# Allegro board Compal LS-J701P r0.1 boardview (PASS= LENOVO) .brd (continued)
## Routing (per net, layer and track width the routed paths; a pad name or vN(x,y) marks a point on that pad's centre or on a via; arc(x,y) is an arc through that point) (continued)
USB3_RX3_CONN1_P1_R: length 13.1
  BOTTOM w0.117: JUSB1.6 19.17,65.66 19.05,65.78 18.22,65.78 17.91,66.09 17.91,67.26 17.71,67.46 17.06,67.46 16.94,67.35 16.94,64.72 17.12,64.54 v4(17.42,64.54) 17.74,64.54 17.99,64.29 17.99,63.52 17.37,62.9 17.11,62.9 16.97,62.76 D1.2 D1.8 15.11,62.76 14.97,62.9 14.74,62.9 RT53.2
USB3_RX3_CONN2_N2: length 11.1
  TOP w0.117: v1(8.78,48.62) 9.61,48.62 10.59,49.59 10.59,49.9 10.61,49.92 10.61,50.47 10.59,50.5 10.59,52.11 10.59,52.11 10.59,52.77 RT56.1
  BOTTOM w0.117: UT2.8 10.43,45.85 10.57,45.99 v4(10.57,47.11) 10.57,47.96 9.55,48.98 9.24,48.98 9.16,48.91 9.16,48.67 9.11,48.62 v1(8.78,48.62)
USB3_RX3_CONN2_N2_R: length 25.6
  TOP w0.117: v1(10.29,58.2) 10.11,58.02 10.11,57.37 10.53,56.95 10.53,56.64 10.67,56.5 D3.1 D3.9 10.67,54.81 10.59,54.73 10.59,54.29 RT56.2
  IN2 w0.127: JUSB2.5 19.17,45.14 19.04,45.01 18.79,45.01 17.8,46 17.8,47.72 16.33,49.18 11.7,49.18 10.22,50.67 10.22,57.14 10.12,57.24 10.12,58.02 v1(10.29,58.2)
USB3_RX3_CONN2_P2: length 11.1
  TOP w0.117: v1(8.78,49.2) 9.03,49.2 9.1,49.14 9.1,48.96 9.21,48.84 9.52,48.84 10.36,49.68 v4(10.36,50.2) 10.36,52.2 10.36,52.77 RT55.1
  BOTTOM w0.117: v1(8.78,49.2) 9.65,49.2 10.79,48.05 10.79,47.41 10.82,47.38 10.82,46.83 10.79,46.81 10.79,45.99 10.93,45.85 UT2.9
USB3_RX3_CONN2_P2_R: length 25.6
  TOP w0.117: RT55.2 10.36,54.29 10.36,54.71 10.17,54.9 D3.8 D3.2 10.17,56.47 10.31,56.61 10.31,56.86 9.89,57.28 9.89,58.02 v1(9.71,58.2)
  IN2 w0.127: v1(9.71,58.2) 9.89,58.02 9.89,57.15 9.99,57.05 9.99,50.57 11.61,48.96 16.24,48.96 17.57,47.63 17.57,45.91 18.7,44.79 18.95,44.79 19.17,44.57 JUSB2.6
USB3_TX3_CONN1_N1: length 18.4
  IN1 w0.102: v1(12.91,61.71) 13.1,61.51 13.3,61.51 13.95,62.16 13.95,72.35 11.58,74.72 11.58,76.05 v1(11.19,76.44)
  BOTTOM w0.117: v1(12.91,61.71) 13.09,61.53 13.28,61.53 RT58.1 ; CT18.2 11.4,76.1 11.4,76.23 v1(11.19,76.44)
USB3_TX3_CONN1_N1_R: length 6.8
  BOTTOM w0.117: RT58.2 14.69,61.63 15,61.63 15.14,61.76 D1.7 D1.4 16.71,61.76 16.94,61.53 v4(17.45,61.53) 17.83,61.53 18.18,61.18 18.18,60.46 18.65,59.99 19.05,59.99 19.17,60.11 JUSB1.8
USB3_TX3_CONN1_P1: length 18.5
  IN1 w0.102: v1(12.91,61.12) 13.1,61.32 13.38,61.32 14.14,62.08 14.14,72.43 11.77,74.8 v1(11.77,76.44)
  BOTTOM w0.117: v1(12.91,61.12) 13.09,61.3 13.28,61.3 RT57.1 ; v1(11.77,76.44) 11.64,76.31 11.64,76.01 CT17.2
USB3_TX3_CONN1_P1_R: length 6.8
  BOTTOM w0.117: RT57.2 14.89,61.4 15,61.4 15.14,61.26 D1.6 D1.5 16.8,61.26 16.85,61.31 17.1,61.31 17.12,61.28 17.76,61.28 17.96,61.09 17.96,60.36 18.55,59.76 19.05,59.76 19.17,59.65 JUSB1.9
USB3_TX3_CONN2_N2: length 12.8
  TOP w0.117: RT59.1 8.94,52.77 8.94,51.9 9.18,51.66 9.37,51.66 v1(9.55,51.84)
  BOTTOM w0.117: v1(9.55,51.84) 9.36,51.65 8.04,51.65 7.92,51.53 7.8,51.4 7.8,50.66 8.11,50.35 8.81,50.35 9.19,49.97 9.78,49.97 9.81,49.95 10.36,49.95 10.38,49.97 v4(11.52,49.97) 12.12,49.97 12.68,49.4 12.68,48.81 12.07,48.19 12.07,47.35 CT25.2
USB3_TX3_CONN2_N2_R: length 30.9
  TOP w0.117: RT59.2 8.94,54.29 8.94,54.7 9.17,54.94 D3.7 D3.4 9.17,56.47 9.03,56.61 9.03,57.2 v1(9.21,57.38)
  IN2 w0.127: JUSB2.8 19.17,39.2 19.04,39.08 18.06,39.08 17.13,40 17.13,47.45 16.06,48.53 11.02,48.53 10.15,49.39 9.03,50.52 9.03,57.21 v1(9.21,57.38)
USB3_TX3_CONN2_P2: length 12.7
  TOP w0.117: v1(9.55,51.25) 9.37,51.43 9.09,51.43 8.71,51.81 8.71,52.77 RT60.1
  BOTTOM w0.117: CT24.2 12.29,47.35 12.29,48.1 12.91,48.72 12.91,49.5 12.21,50.2 11.82,50.2 11.8,50.22 11.25,50.22 11.22,50.2 v4(10.08,50.2) 9.28,50.2 8.91,50.57 8.2,50.57 8.02,50.75 8.02,51.31 8.14,51.43 9.37,51.43 v1(9.55,51.25)
USB3_TX3_CONN2_P2_R: length 30.9
  TOP w0.117: RT60.2 8.71,54.29 8.71,54.7 8.67,54.75 D3.6 D3.5 8.67,56.5 8.81,56.64 8.81,57.2 v1(8.63,57.38)
  IN2 w0.127: v1(8.63,57.38) 8.81,57.21 8.81,50.42 9.61,49.62 10.93,48.3 15.97,48.3 16.91,47.36 16.91,39.91 17.97,38.85 19.04,38.85 19.17,38.72 JUSB2.9
USB3_TX3_MUX_N1_C: length 1.5
  BOTTOM w0.117: CT18.1 11.34,75.16 11.34,74.64 11.2,74.5 UT1.11
USB3_TX3_MUX_N2_C: length 1.5
  BOTTOM w0.117: UT2.11 11.93,45.85 12.07,45.99 12.07,46.41 CT25.1
USB3_TX3_MUX_P1_C: length 1.5
  BOTTOM w0.117: UT1.12 11.7,74.5 11.56,74.64 11.56,75.1 CT17.1
USB3_TX3_MUX_P2_C: length 1.5
  BOTTOM w0.117: UT2.12 12.43,45.85 12.3,45.99 12.3,46.42 CT24.1
USB20_N1: length 52.4
  TOP w0.117: L1.1 8.65,47.21 v1(8.61,47.25)
  IN1 w0.102: v1(26.61,8.98) 26.43,9.16 26.43,9.51 26.22,9.72 24.87,9.72 23.26,11.33 23.26,14.44 20.93,16.77 20.93,19.59 20.59,19.94 20.59,20.19 19.68,21.1 18.99,21.1 10.52,29.57 10.52,35.75 10.27,36.01 10.27,41.5 9.71,42.06 9.71,46.49 9.17,47.02 8.83,47.02 v1(8.61,47.25)
  BOTTOM w0.117: v1(26.61,8.98) 26.43,9.16 26.43,9.36 26.5,9.43 28.3,9.43 28.72,9.99 28.96,10.02 JIO2.2
USB20_N1_R: length 27.4
  TOP w0.117: L1.2 11,47.07 11.97,47.07 12.09,47.19 12.09,47.89 D2.6 12.4,47.19 12.52,47.07 12.82,47.07 v1(13,47.25)
  IN1 w0.102: v1(13,47.25) 12.92,47.17 12.78,47.17 12.7,47.25 12.7,57.72 16.1,61.12 16.99,61.12 18.24,62.37 18.24,63.58 18.45,63.78 19.44,63.78 20.67,62.56 JUSB1.2
USB20_N2: length 16.1
  TOP w0.117: v1(13.61,22.88) 13.43,22.7 13.14,22.7 13.12,22.73 12.57,22.73 12.54,22.7 11.07,22.7 10.24,23.53 10.24,29.05 10.72,29.52 v4(11.41,29.52) 12.11,29.52 13.53,30.94 13.53,31.22 L2.4
  BOTTOM w0.117: v1(13.61,22.88) 13.71,22.78 14.17,22.78 14.6,22.34 14.62,21.99 14.55,21.91 14.55,21.88 14.54,21.86 14.56,21.65 14.38,21.41 JIO2.39
USB20_N2_R: length 22.2
  TOP w0.117: L2.3 13.67,32.02 13.44,32.25 13.44,32.51 v1(13.71,32.78) ; v1(14.23,37.54) 14.24,37.54 14.42,37.36 14.53,37.36 14.64,37.48 D5.4 14.96,37.99 14.96,37.54 15.16,37.34 15.5,37.34 v1(15.77,37.6)
  IN1 w0.102: v1(15.77,37.6) 15.47,37.3 15.42,37.3 15.19,37.53 15.19,41.05 17.06,42.92 19.51,42.92 20.67,41.76 JUSB2.2 ; v1(13.71,32.78) 13.39,33.1 13.39,33.15 15.26,35.02 15.26,36.24 15.24,36.25 15.24,36.66 14.6,37.3 14.46,37.3 v1(14.23,37.54)
USB20_P1: length 52.5
  TOP w0.117: L1.4 10.19,46.71 9.92,46.98 9.92,46.98 9.06,46.98 8.97,46.89 8.97,46.7 8.93,46.66 v1(8.61,46.66)
  IN1 w0.102: v1(26.03,9.01) 26.24,9.23 26.24,9.43 26.14,9.53 24.79,9.53 23.07,11.25 23.07,14.37 20.74,16.69 20.74,19.51 20.4,19.86 20.4,20.11 19.6,20.91 18.91,20.91 10.33,29.49 10.33,35.68 10.08,35.93 10.08,41.42 9.52,41.98 9.52,46.41 9.09,46.83 8.78,46.83 v1(8.61,46.66)
  BOTTOM w0.117: v1(26.03,9.01) 26.21,9.19 26.21,9.46 26.4,9.65 28.19,9.65 28.54,10.12 28.52,10.27 28.75,10.58
USB20_P1_R: length 27.4
  TOP w0.117: v1(13,46.66) 12.82,46.85 12.52,46.85 12.4,46.73 D2.1 12.09,46.02 12.09,46.73 11.97,46.84 11,46.84 L1.3
  IN1 w0.102: v1(13,46.66) 12.8,46.86 12.8,46.87 12.51,47.17 12.51,57.79 16.02,61.31 16.91,61.31 18.05,62.45 18.05,63.66 18.37,63.97 19.52,63.97 20.03,63.47 20.24,63.47 JUSB1.3
USB20_P2: length 16
  TOP w0.117: L2.1 13.3,31.22 13.3,31.03 12.02,29.75 11.71,29.75 11.69,29.77 11.14,29.77 11.11,29.75 10.62,29.75 10.02,29.14 10.02,23.43 10.97,22.48 v4(12.84,22.48) 13.43,22.48 v1(13.61,22.3)
  BOTTOM w0.117: v1(13.61,22.3) 13.86,22.55 14.07,22.55 14.38,22.24 14.39,22.07 14.36,22.03 14.22,22.01 13.98,21.71 JIO2.40
USB20_P2_R: length 22.2
  TOP w0.117: v1(15.77,37.02) 15.67,37.11 15.08,37.11 14.96,37 14.96,36.12 D5.3 14.64,36.95 14.46,37.14 14.42,37.14 v1(14.24,36.95) ; v1(13.12,32.78) 13.17,32.74 L2.2
  IN1 w0.102: v1(14.24,36.95) 14.4,37.11 14.52,37.11 15.05,36.58 15.05,36.17 15.06,36.16 15.06,35.1 13.2,33.23 13.2,32.86 v1(13.12,32.78) ; v1(15.77,37.02) 15.67,37.11 15.34,37.11 15,37.45 15,41.12 16.99,43.11 19.59,43.11 20.12,42.58 20.57,42.58 20.67,42.68 JUSB2.3
N111995914: length 3.8
  BOTTOM w0.117: UT1.7 9.2,74.97 RT1.1 8.29,75.39 7.57,76.1 v3(7.57,76.74)
N112008691: length 2.4
  BOTTOM w0.254: UCR1.9 24.78,19.71 24.66,19.59 24.66,19.27
  BOTTOM w0.305: RR1.1 24.67,18.31 24.72,18.36 24.72,19.21 24.66,19.27
N112008714: length 4.9
  BOTTOM w0.117: UCR1.28 30.11,21.31 30.44,20.98 30.44,18.08 RR2.1
N112008722: length 3.1
  IN2 w0.127: v1(24.21,18.57) 24.55,18.91 24.55,21.13 24.27,21.42 v1(24.27,21.43)
N112008758: length 2.5
  BOTTOM w0.117: CR14.1 27.07,24.31 27.57,23.82 28.26,23.82 28.53,23.55 UCR1.24
N112013174: length 6.3
  BOTTOM w0.117: RT32.1 7.09,46.12 ; 7.09,46.12 7.53,46.12 7.53,46.12 9.56,46.12 9.93,45.74 UT2.7 ; 7.09,46.12 7.64,46.66 7.64,47.4 v3(6.75,48.29)

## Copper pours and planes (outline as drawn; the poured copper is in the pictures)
+3VALW on BOTTOM: 8.02,70.77 8.72,70.77 8.84,70.64 8.84,67.59 8.65,67.4 7.51,67.4 7.38,67.53 7.38,68.93 7.7,69.25 7.7,70.45
+3VALW on BOTTOM: 12.78,44.42 12.78,45.62 13.48,46.32 15.7,46.32 16.27,45.75 16.27,44.23 16.15,44.1 15.19,44.1 15.13,44.16 15.13,45.43 14.94,45.62 14.11,45.62 13.67,45.18 13.67,44.35 13.61,44.29 12.91,44.29
+3VALW on BOTTOM: 10.05,40.16 10.3,40.16 11,39.46 11,39.02 11.64,38.38 11.64,38.13 11.51,38 10.3,38 10.11,38.19 10.11,39.34 9.92,39.53 9.92,40.04
+3VALW on BOTTOM: 12.34,74.71 13.04,74.71 13.16,74.58 13.16,73.25 12.91,72.99 12.08,72.99 12.02,73.06 12.02,73.5 12.15,73.63 12.15,74.52
+3VALW on IN2: 5.86,76.36 15.07,76.36 15.96,75.47 15.96,68.42 15.64,68.1 6.11,68.1 4.72,69.5 4.72,75.21
+3VALW on IN2: 9.03,46.07 14.81,46.07 16.27,44.61 16.27,38.51 16.02,38.26 11.83,38.26 11.57,38 11.19,38 8.78,40.42 8.78,45.81
+3VL on TOP (solid shape): 30.69,83.85 30.69,82.14 30.4,81.85 29.9,81.85 29.74,82.02 29.74,82.47 29.74,82.64 29.16,83.22 29.16,83.85 29.48,84.17 30.37,84.17
+3VS on BOTTOM: 21.13,16.81 21.11,16.94 20.61,17.31 20.44,17.29 19.85,16.5 19.07,16.39 17.97,16.39 17.96,16.38 17.26,16.38 17.1,16.22 17.1,14.95 17.16,14.89 17.67,14.89 17.73,14.83 18.49,14.83 19.03,15.36 20.16,15.52
+3VS on BOTTOM: 29.23,26.76 27.83,26.76 27.39,26.32 27.39,25.87 27.58,25.68 28.4,25.68 28.59,25.87 29.48,25.87 29.61,26 29.61,26.38
+3VS on BOTTOM: 28.91,17.05 30.24,17.05 30.37,16.92 30.37,15.33 28.47,13.43 27.39,13.43 27.13,13.68 27.13,14.32 28.72,15.91 28.72,16.86
+3VS on IN1: 28.59,26.45 29.42,26.45 30.69,25.18 30.69,16.73 29.8,15.84 28.85,15.84 28.4,16.29 28.4,19.59 28.59,19.78 28.59,22.51 29.29,23.21 29.29,24.6 28.4,25.49 28.4,26.26
+3VS on IN2: 27.39,14.38 28.21,14.38 28.66,13.94 28.66,13.17 28.21,12.73 27.51,12.73 27.26,12.98 27.26,14.25
+3VS on IN2: 17.73,16.29 18.31,16.29 19.45,15.14 19.45,14.7 19,14.25 18.37,14.25 17.48,15.14 17.48,16.03
+3VS_SD on BOTTOM: 27.58,25.05 30.56,25.05 31.01,24.6 31.01,22.06 30.5,21.56 28.78,21.56 28.72,21.62 28.72,21.81 28.78,21.87 29.55,21.87 29.74,22.06 29.74,22.7 28.28,24.16 27.7,24.16 27.51,24.35 27.51,24.99
+3VS_SD on BOTTOM: 24.51,20.65 25.46,20.65 25.54,20.57 25.54,20.41 25.51,20.38 24.57,20.38 23.82,19.63 23.82,19.15 23.62,18.95 23.07,18.95 23,19.02 23,19.54 23,19.55 23,19.63 22.82,19.81 22.82,20.43 22.58,20.67 22.58,20.87 22.69,20.97 23.05,20.97 23.14,20.88 23.14,20.49 23.32,20.31 24.17,20.31
+5VALW_USB1 on TOP: 12.4,57.24 12.08,57.56 12.08,59.78 12.46,60.16 20.9,60.16 21.21,59.85 21.21,57.93 20.53,57.24
+5VALW_USB1 on BOTTOM: 22.1,13.81 21.99,13.81 21.49,13.31 21.23,13.31 20.8,12.88 20.8,12.65 21.2,12.25 21.21,12.25 22.45,11.01 23.34,11.01 24.72,12.39 25.53,13.47 25.52,13.61 23.78,14.91 23.62,14.88 22.82,13.8
+5VALW_USB1 on IN2: 15.89,57.24 15.51,57.62 15.51,59.97 15.7,60.16 21.04,60.16 21.21,59.99 21.21,58.18 20.27,57.24
+5VALW_USB1 on IN3: 16,9.49 9.49,16 9.49,47.37 10.5,48.38 10.5,57.18 13.48,60.16 21.04,60.16 21.21,59.99 21.21,58.18 20.27,57.24 15.45,57.24 13.54,55.34 13.54,45.74 14.76,44.52 14.76,40.98 13.54,39.76 13.54,25.89 16.08,23.35 16.08,15.21 18.18,13.11 19.67,13.11 19.77,13.02 20.88,13.02 21.93,14.06 23.89,14.06 24.34,13.62 24.34,11.78 22.05,9.49
+5VALW_USB2 on IN3 (solid shape): outline of 458 points within 13.73,13.11 21.47,42
+5VALW_USB2 on TOP: 10.75,28.48 14.37,28.48 14.69,28.16 14.69,26.89 14.56,26.76 10.81,26.76 10.69,26.89 10.69,28.41
+5VALW_USB2 on TOP: 18.18,36.48 16.59,38.07 16.59,41.88 16.72,42 18.75,42 21.21,39.54 21.21,37.36 20.34,36.48
+5VALW_USB2 on BOTTOM: 22.45,15.82 22.01,15.25 21.7,15.21 21.69,15.2 21.35,15.2 20.53,14.38 20.05,13.9 20.05,13.45 20.53,12.97 20.78,12.97 21.24,13.43 21.48,13.43 21.99,13.94 22.71,13.94 23.48,14.95 23.52,15.12 23.53,15.17 23.14,15.46 22.64,15.85
+5VALW_USB2 on IN1: 18.18,36.48 17.42,37.24 17.42,41.5 17.92,42 18.75,42 21.21,39.54 21.21,37.36 20.34,36.48
GND on TOP (solid shape): 32.2,1.33 31.97,0.77 31.41,0.53 19,0.53 18.95,0.4 18.84,0.26 18.67,0.2 15.01,0.2 14.82,0.27 14.72,0.45 14.12,0.99 13.61,1.6 13.61,2.19 14.05,2.63 16.46,2.63 16.97,3.14 17.35,3.14 17.73,2.76 19.7,2.76 21.64,4.7 25.07,4.7 27.07,6.7 32.2,6.7
GND on TOP (solid shape): 21.21,56.14 21.8,55.45 22.58,55.9 22.59,55.94 28.86,55.94 28.86,49.04 22.59,49.04 22.58,49.08 21.8,49.53 21.21,48.84 21.21,47.78 17.04,47.78 14.11,50.7 13.2,50.7 12.38,51.52 12.38,54.9 13.91,56.42 13.91,56.74 13.68,56.96 13.37,56.96 11.93,55.53 11.85,55.53 11.74,55.63 11.74,57.13 11.79,57.18 21.21,57.18
GND on TOP (solid shape): outline of 443 points within 3.63,47.34 11.9,59.4
GND on TOP (solid shape): outline of 1051 points within 0.2,0.2 32.2,86.94
GND on BOTTOM (solid shape): 10.96,39.88 10.99,39.85 11.26,39.58 11.29,39.55 11.94,38.9 11.94,38.68 11.65,38.68 11.62,38.63 11.56,38.64 11.13,39.07 11.13,39.52 10.81,39.83 10.81,39.94 10.9,39.94
GND on BOTTOM (solid shape): 32.2,1.33 31.97,0.77 31.41,0.53 19,0.53 18.95,0.4 18.84,0.26 18.67,0.2 15.01,0.2 14.82,0.27 14.72,0.45 14.12,0.99 13.61,1.6 13.61,2.19 14.11,2.7 16.53,2.7 16.97,3.14 17.35,3.14 17.73,2.76 19.7,2.76 23.64,6.7 32.2,6.7
GND on BOTTOM (solid shape): 11.65,37.87 11.65,37.46 11.95,37.46 12.12,37.29 12.12,37.1 11.38,36.37 11.38,36.21 11.38,36.16 11.38,35.78 11.38,35.74 11.38,26.48 15.23,22.63 15.23,22.59 15.2,22.56 15.2,21.82 15.23,21.8 15.23,21.72 15.18,21.66 15.14,21.68 15.07,21.7 14.99,21.71 14.93,21.73 14.89,21.79 14.86,21.86 14.82,21.92 14.81,21.93 14.79,22.42 14.24,22.96 13.96,22.96 13.94,23 13.43,23.19 13.33,22.65 13.36,22.59 13.33,22.52 13.28,22.15 13.6,21.94 13.69,21.88 13.68,21.78 13.52,21.57 13.49,21.27 13.76,21.12 13.83,21.1 13.97,20.88 14.23,20.8 14.37,20.57 14.56,20.52 13.54,19.5 13,19.5 12.41,20.1 12.41,21.81 12.4,21.82 12.4,23.59 11.79,24.2 11.79,24.22 11.7,24.43 11.49,24.5 10.4,24.5 10.35,23.99 10.3,23.47 8.29,23.47 8.58,30.49 7.83,37.47 9.86,37.47 9.89,37.31 9.95,37.25 10.73,37.25 10.81,37.33 10.81,37.88 11.56,37.88 11.59,37.9
GND on BOTTOM (solid shape): outline of 98 points within 0,49.47 17.77,80.86
GND on BOTTOM (solid shape): outline of 3084 points within 0.2,0.2 32.2,86.94
GND on IN1 (solid shape): 21.21,56.14 21.81,55.44 22.59,55.94 28.86,55.94 28.86,49.04 22.59,49.04 21.81,49.54 21.21,48.84 21.21,47.78 17.04,47.78 13.16,51.66 13.16,55.02 15.32,57.18 21.21,57.18
GND on IN1 (solid shape): outline of 167 points within 0.2,0.2 32.2,86.94
GND on IN2 (solid shape): 15.84,57.12 20.33,57.12 20.39,57.18 21.21,57.18 21.21,56.14 21.8,55.45 22.58,55.9 22.59,55.94 28.86,55.94 28.86,49.04 22.59,49.04 22.58,49.08 21.8,49.53 21.21,48.84 21.21,47.78 18.19,47.78 13.16,52.81 13.16,55.02 15.32,57.18 15.78,57.18
GND on IN2 (solid shape): outline of 768 points within 0.2,0.2 32.2,86.94
GND on IN3 (solid shape): 21.21,56.14 21.8,55.45 22.58,55.9 22.59,55.94 28.86,55.94 28.86,49.04 22.59,49.04 22.58,49.08 21.8,49.53 21.21,48.84 21.21,47.78 17.99,47.78 16.4,49.37 15.45,49.37 14.01,50.81 14.01,55.25 15.64,56.88 18.81,56.88 19.04,57.12 20.33,57.12 20.39,57.18 21.21,57.18
GND on IN3 (solid shape): outline of 767 points within 0.2,0.2 32.2,86.94
GND on TOP: 10.69,25.68 13.67,25.68 13.8,25.56 13.8,23.65 13.67,23.53 10.81,23.53 10.62,23.72 10.62,25.62
GND on TOP: 12.46,66.45 15.96,66.45 16.46,65.94 16.46,64.23 15.96,63.72 12.4,63.72 12.21,63.91 12.21,66.2
GND on BOTTOM: 26.12,13.24 28.47,13.24 29.1,12.6 29.1,11.55 29.1,11.55 28.34,10.51 27.92,9.97 27.86,9.89 26.13,9.89 26.02,9.78 25.18,9.78 24.76,10.2 24.76,11.55 25.81,12.85
GND on GND1: outline of 85 points within 0.2,0.2 32.2,86.94
GND on IN1: outline of 89 points within 0.2,0.2 32.2,86.94 ; 5 cut-outs
GND on GND2: outline of 84 points within 0.2,0.2 32.2,86.94
GND on IN2: outline of 87 points within 0.2,0.2 32.2,86.94 ; 4 cut-outs
GND on IN3: outline of 87 points within 0.2,0.2 32.2,86.94 ; 9 cut-outs
GND on GND3: outline of 83 points within 0.2,0.2 32.2,86.94
+CARD_3V3 on IN1 (solid shape): 14.43,15.52 14.43,14.51 14.05,14.13 13.23,14.13 12.84,14.51 12.84,15.91 12.97,16.03 13.92,16.03
+CARD_3V3 on TOP: 12.4,15.91 12.4,14.51 12.65,14.25 15.89,14.25 16.21,14.57 16.21,15.14 15.32,16.03 12.53,16.03
+CARD_3V3 on BOTTOM: 24.07,21.11 25.48,21.11 25.61,20.99 25.61,20.86 25.48,20.73 24.4,20.73 24.05,20.38 23.44,20.38 23.25,20.57 23.25,20.9 23.29,20.95 23.91,20.95
+CARD_3V3 on IN1: 23.47,21.04 24.48,21.04 24.63,20.9 24.63,19.66 24.55,19.59 23.51,19.59 23.27,19.82 23.27,20.85
Net_2 on TOP (solid shape): 10.01,60.64 5.01,60.64 5.01,65.64 10.01,65.64
PWR_LED_AMBER# on TOP: 13.58,49.88 14.4,49.26 15.35,48.87 15.4,48.82 15.4,47.32 15.09,47.01 14.17,47.01 13.67,47.51 13.67,47.69 13.74,47.81 13.76,47.94 13.76,48.35 13.79,48.4 13.85,48.39 13.9,48.34 13.9,47.94 14.3,47.53 14.71,47.94 14.71,48.47 14.47,48.84 14.04,48.79 14.01,48.76 13.79,48.97 13.72,49.01 13.64,49.02 13.62,49.02 13.32,49.32 13.32,49.88
N112008722 on BOTTOM: 24.55,20.25 25.48,20.25 25.55,20.17 25.55,20.05 25.48,19.98 24.71,19.98 24.4,19.67 24.4,18.4 24.25,18.25 23.41,18.25 23.27,18.39 23.27,18.78 23.31,18.82 23.72,18.82 23.96,19.06 23.96,19.66
N112008722 on BOTTOM: 24.73,21.87 25.51,21.87 25.56,21.82 25.56,21.61 25.51,21.56 24.64,21.56 24.35,21.85 23.99,21.85 23.94,21.8 23.94,21.71 24,21.65 24.39,21.65 24.51,21.54 24.51,21.22 24.38,21.1 23.91,21.1 23.81,21 23.27,21 23.14,21.13 23.14,21.67 23.35,21.87 23.35,22.31 23.42,22.38 24.22,22.38 24.73,21.87

Small or netless copper shapes (teardrops, artwork), in the pictures only: 4 on TOP, 5 on BOTTOM

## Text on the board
Ref Des/Silkscreen Bottom: In Taiwan
User.Comments: LS-J701P | 2019-11-28 | 2020-11-28 | Peter | FLMA0 | 0.1
Ref Des/Silkscreen Top: LS-J701P
User.30: GND4
User.31: GND5
User.32: FIGURE | SIZE | 8.0 | 31.0 | 91.0 | 102.0 | 110.0 | 47.0 | 67.0 | 79.0x31.0 | 94.0x31.0 | 110.0x91.0 | 134.0x24.0 | DRILL CHART: TOP to BOTTOM | ALL UNITS ARE IN MILS | TOLERANCE | +3.0/-3.0 | +2.0/-2.0 | PLATED | NON-PLATED | QTY | 316 | 18 | 1 | 2 | 4
User.33: LAYER | L3 | L4 | L5 | L6 | L7 | L8 | L1 | L2 | NO | 0_9mm-8L(4mil 50ohm)-Top G-V IN1 G-V IN2 IN3 G-V Bot-180307 | IN3 | GND3 | GND2 | BOT(50,85 ohm) | DB-2759P | 5 mil | 4.6 mil | 4 mil | 4.6/4.2 | 4/3.5 | 5/3.9 | REF | L4/L7 | L2/L4
